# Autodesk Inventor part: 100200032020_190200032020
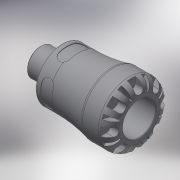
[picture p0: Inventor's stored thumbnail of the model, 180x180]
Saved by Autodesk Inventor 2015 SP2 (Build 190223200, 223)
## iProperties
Created: 2016-12
Part Number: 100200032020_190200032020
Material: Generic
Description: PLASSON MALE ADAPTOR 32X2" SERIES 1
Document SubType Name: Modeling
Designer: KIM
Mass: 447.839 g
Surface Area: 722.341 cm^2
Volume: 447.839 cm^3
Density: 1 g/cm^3
Appearance: Default
Author: KIM
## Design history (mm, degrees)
derived "1002.ipt"
feature "Solid1::1002.ipt"
tag "TaggingFeature1"
body "Solid1"
other parameters: "d0" = 97, "d1" = 23.1, "d2" = 32, "d4" = 58, "d6" = 55, "d8" = 55.1, "d13" = 7.2, "d14" = 7.2, "d15" = 0, "d17" = 360 deg, "d19" = 8 deg, "d20" = 0.64, "d21" = 0.64, "d22" = 8 deg, "d24" = 0, "d26" = 360 deg, "d32" = 0.925, "d33" = 5.8, "d34" = 59.614, "d35" = 4, "d38" = 25, "d39" = 1.78842, "d42" = 11.2, "d43" = 7.36, "d45" = 14.112, "d46" = 0, "d59" = 360 deg, "d61" = 9.52, "d62" = 0.64, "d64" = 0, "d65" = 0.58, "d_" = 32, "E_" = 58, "H_" = 97, "l_" = 55, "R_" = 59.614, "l_2" = 25, "d9" = 9, "d11" = 58
